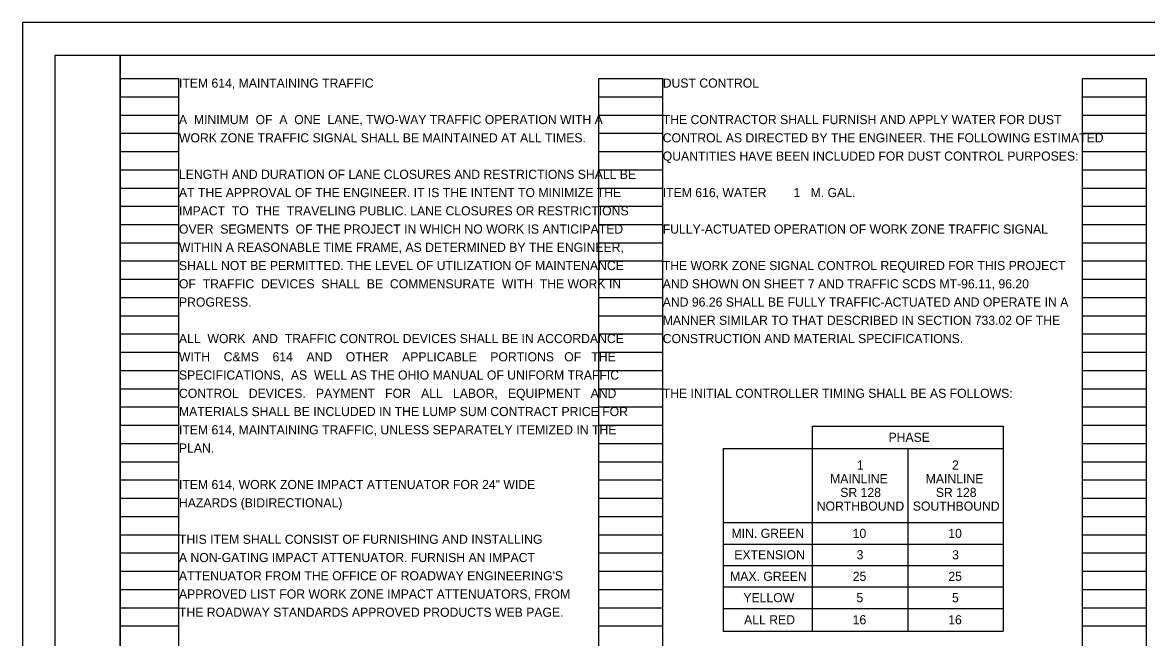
# Model space of a CAD drawing. Extents: x 0 to 34, y 0 to 22.
# Drawn here: x 0 to 17.24, y 12.56 to 22 of the extents above; entities that cross this region are included whole.
import ezdxf

# ---------------------------------------------------------------- set-up
doc = ezdxf.new("R2010")
doc.units = 0
for name, color, linetype in [('SH_Border', 7, 'Continuous'), ('SH_Cut_Line', 7, 'Continuous'), ('SH_Data', 7, 'Continuous'), ('SH_Text', 7, 'Continuous')]:
    doc.layers.add(name, color=color, linetype=linetype)

msp = doc.modelspace()

# ---------------------------------------------------------------- linework, layer by layer
at = {"layer": 'SH_Border'}
for points in [[(0.5, 21.5), (1.5, 21.5), (1.5, 0.5), (0.5, 0.5)], [(1.5, 21.5), (33.5, 21.5), (33.5, 0.5), (1.5, 0.5)]]:
    msp.add_lwpolyline(points, close=True, dxfattribs=at)
at = {"layer": 'SH_Cut_Line'}
msp.add_lwpolyline([(0, 0), (34, 0), (34, 22), (0, 22)], close=True, dxfattribs=at)
at = {"layer": 'SH_Data'}
for p, q in [((1.5, 0.98), (1.5, 21.14)), ((1.5, 21.14), (2.4, 21.14)), ((2.4, 0.98), (2.4, 21.14)), ((8.84, 0.98), (8.84, 21.14)), ((8.84, 21.14), (9.82, 21.14)), ((9.82, 0.98), (9.82, 21.14)), ((16.26, 0.98), (16.26, 21.14)), ((16.26, 21.14), (17.24, 21.14)), ((17.24, 0.98), (17.24, 21.14)), ((1.5, 20.86), (2.4, 20.86)), ((8.84, 20.86), (9.82, 20.86)), ((16.26, 20.86), (17.24, 20.86)), ((1.5, 20.58), (2.4, 20.58)), ((8.84, 20.58), (9.82, 20.58)), ((16.26, 20.58), (17.24, 20.58)), ((1.5, 20.3), (2.4, 20.3)), ((8.84, 20.3), (9.82, 20.3)), ((16.26, 20.3), (17.24, 20.3)), ((1.5, 20.02), (2.4, 20.02)), ((8.84, 20.02), (9.82, 20.02)), ((16.26, 20.02), (17.24, 20.02)), ((1.5, 19.74), (2.4, 19.74)), ((8.84, 19.74), (9.82, 19.74)), ((16.26, 19.74), (17.24, 19.74)), ((1.5, 19.46), (2.4, 19.46)), ((8.84, 19.46), (9.82, 19.46)), ((16.26, 19.46), (17.24, 19.46)), ((1.5, 19.18), (2.4, 19.18)), ((8.84, 19.18), (9.82, 19.18)), ((16.26, 19.18), (17.24, 19.18)), ((1.5, 18.9), (2.4, 18.9)), ((8.84, 18.9), (9.82, 18.9)), ((16.26, 18.9), (17.24, 18.9)), ((1.5, 18.62), (2.4, 18.62)), ((8.84, 18.62), (9.82, 18.62)), ((16.26, 18.62), (17.24, 18.62)), ((1.5, 18.34), (2.4, 18.34)), ((8.84, 18.34), (9.82, 18.34)), ((16.26, 18.34), (17.24, 18.34)), ((1.5, 18.06), (2.4, 18.06)), ((8.84, 18.06), (9.82, 18.06)), ((16.26, 18.06), (17.24, 18.06)), ((1.5, 17.78), (2.4, 17.78)), ((8.84, 17.78), (9.82, 17.78)), ((16.26, 17.78), (17.24, 17.78)), ((1.5, 17.5), (2.4, 17.5)), ((8.84, 17.5), (9.82, 17.5)), ((16.26, 17.5), (17.24, 17.5)), ((1.5, 17.22), (2.4, 17.22)), ((8.84, 17.22), (9.82, 17.22)), ((16.26, 17.22), (17.24, 17.22)), ((1.5, 16.94), (2.4, 16.94)), ((8.84, 16.94), (9.82, 16.94)), ((16.26, 16.94), (17.24, 16.94)), ((1.5, 16.66), (2.4, 16.66)), ((8.84, 16.66), (9.82, 16.66)), ((16.26, 16.66), (17.24, 16.66)), ((1.5, 16.38), (2.4, 16.38)), ((8.84, 16.38), (9.82, 16.38)), ((16.26, 16.38), (17.24, 16.38)), ((1.5, 16.1), (2.4, 16.1)), ((8.84, 16.1), (9.82, 16.1)), ((16.26, 16.1), (17.24, 16.1)), ((1.5, 15.82), (2.4, 15.82)), ((8.84, 15.82), (9.82, 15.82)), ((12.112, 15.808), (15.044, 15.808)), ((12.112, 15.808), (12.112, 12.662)), ((15.044, 15.808), (15.044, 12.662)), ((16.26, 15.82), (17.24, 15.82)), ((1.5, 15.54), (2.4, 15.54)), ((8.84, 15.54), (9.82, 15.54)), ((16.26, 15.54), (17.24, 15.54)), ((10.745, 15.462), (15.044, 15.462)), ((10.745, 15.462), (10.745, 12.662)), ((13.578, 15.462), (13.578, 14.326)), ((1.5, 15.26), (2.4, 15.26)), ((8.84, 15.26), (9.82, 15.26)), ((16.26, 15.26), (17.24, 15.26)), ((1.5, 14.98), (2.4, 14.98)), ((8.84, 14.98), (9.82, 14.98)), ((16.26, 14.98), (17.24, 14.98)), ((1.5, 14.7), (2.4, 14.7)), ((8.84, 14.7), (9.82, 14.7)), ((16.26, 14.7), (17.24, 14.7)), ((1.5, 14.42), (2.4, 14.42)), ((8.84, 14.42), (9.82, 14.42)), ((10.745, 14.326), (15.044, 14.326)), ((13.578, 14.326), (13.578, 12.662)), ((16.26, 14.42), (17.24, 14.42)), ((1.5, 14.14), (2.4, 14.14)), ((8.84, 14.14), (9.82, 14.14)), ((16.26, 14.14), (17.24, 14.14)), ((10.745, 13.996), (15.044, 13.996)), ((1.5, 13.86), (2.4, 13.86)), ((8.84, 13.86), (9.82, 13.86)), ((16.26, 13.86), (17.24, 13.86)), ((10.745, 13.667), (15.044, 13.667)), ((1.5, 13.58), (2.4, 13.58)), ((8.84, 13.58), (9.82, 13.58)), ((16.26, 13.58), (17.24, 13.58)), ((1.5, 13.3), (2.4, 13.3)), ((8.84, 13.3), (9.82, 13.3)), ((10.745, 13.338), (15.044, 13.338)), ((16.26, 13.3), (17.24, 13.3)), ((1.5, 13.02), (2.4, 13.02)), ((8.84, 13.02), (9.82, 13.02)), ((10.745, 13.008), (15.044, 13.008)), ((16.26, 13.02), (17.24, 13.02)), ((1.5, 12.74), (2.4, 12.74)), ((8.84, 12.74), (9.82, 12.74)), ((10.745, 12.662), (15.044, 12.662)), ((16.26, 12.74), (17.24, 12.74))]:
    msp.add_line(p, q, dxfattribs=at)

# ---------------------------------------------------------------- texts
at = {"layer": 'SH_Text'}
for s, p in [('ITEM 614, MAINTAINING TRAFFIC', (2.4, 21)), ('DUST CONTROL', (9.82, 21)), ('A  MINIMUM  OF  A  ONE  LANE, TWO-WAY TRAFFIC OPERATION WITH A', (2.4, 20.44)), ('THE CONTRACTOR SHALL FURNISH AND APPLY WATER FOR DUST', (9.82, 20.44)), ('WORK ZONE TRAFFIC SIGNAL SHALL BE MAINTAINED AT ALL TIMES.', (2.4, 20.16)), ('CONTROL AS DIRECTED BY THE ENGINEER. THE FOLLOWING ESTIMATED', (9.82, 20.16)), ('QUANTITIES HAVE BEEN INCLUDED FOR DUST CONTROL PURPOSES:', (9.82, 19.88)), ('LENGTH AND DURATION OF LANE CLOSURES AND RESTRICTIONS SHALL BE', (2.4, 19.6)), ('AT THE APPROVAL OF THE ENGINEER. IT IS THE INTENT TO MINIMIZE THE', (2.4, 19.32)), ('ITEM 616, WATER        1   M. GAL.', (9.82, 19.32)), ('IMPACT  TO  THE  TRAVELING PUBLIC. LANE CLOSURES OR RESTRICTIONS', (2.4, 19.04)), ('OVER  SEGMENTS  OF THE PROJECT IN WHICH NO WORK IS ANTICIPATED', (2.4, 18.76)), ('FULLY-ACTUATED OPERATION OF WORK ZONE TRAFFIC SIGNAL', (9.82, 18.76)), ('WITHIN A REASONABLE TIME FRAME, AS DETERMINED BY THE ENGINEER,', (2.4, 18.48)), ('SHALL NOT BE PERMITTED. THE LEVEL OF UTILIZATION OF MAINTENANCE', (2.4, 18.2)), ('THE WORK ZONE SIGNAL CONTROL REQUIRED FOR THIS PROJECT', (9.82, 18.2)), ('OF  TRAFFIC  DEVICES  SHALL  BE  COMMENSURATE  WITH  THE WORK IN', (2.4, 17.92)), ('AND SHOWN ON SHEET 7 AND TRAFFIC SCDS MT-96.11, 96.20', (9.82, 17.92)), ('PROGRESS.', (2.4, 17.64)), ('AND 96.26 SHALL BE FULLY TRAFFIC-ACTUATED AND OPERATE IN A', (9.82, 17.64)), ('MANNER SIMILAR TO THAT DESCRIBED IN SECTION 733.02 OF THE', (9.82, 17.36)), ('ALL  WORK  AND  TRAFFIC CONTROL DEVICES SHALL BE IN ACCORDANCE', (2.4, 17.08)), ('CONSTRUCTION AND MATERIAL SPECIFICATIONS.', (9.82, 17.08)), ('WITH    C&MS    614    AND    OTHER    APPLICABLE    PORTIONS   OF   THE', (2.4, 16.8)), ('SPECIFICATIONS,  AS  WELL AS THE OHIO MANUAL OF UNIFORM TRAFFIC', (2.4, 16.52)), ('CONTROL   DEVICES.   PAYMENT   FOR   ALL   LABOR,   EQUIPMENT   AND', (2.4, 16.24)), ('THE INITIAL CONTROLLER TIMING SHALL BE AS FOLLOWS:', (9.82, 16.24)), ('MATERIALS SHALL BE INCLUDED IN THE LUMP SUM CONTRACT PRICE FOR', (2.4, 15.96)), ('ITEM 614, MAINTAINING TRAFFIC, UNLESS SEPARATELY ITEMIZED IN THE', (2.4, 15.68)), ('PHASE', (13.283, 15.565)), ('PLAN.', (2.4, 15.4)), ('1', (12.799, 15.139)), ('2', (14.258, 15.139)), ('MAINLINE', (12.387, 14.929)), ('MAINLINE', (13.853, 14.929)), ('ITEM 614, WORK ZONE IMPACT ATTENUATOR FOR 24" WIDE', (2.4, 14.84)), ('SR 128', (12.543, 14.719)), ('SR 128', (14.009, 14.719)), ('HAZARDS (BIDIRECTIONAL)', (2.4, 14.56)), ('NORTHBOUND', (12.182, 14.509)), ('SOUTHBOUND', (13.656, 14.509)), ('THIS ITEM SHALL CONSIST OF FURNISHING AND INSTALLING', (2.4, 14)), ('MIN. GREEN', (10.875, 14.091)), ('10', (12.733, 14.091)), ('10', (14.199, 14.091)), ('A NON-GATING IMPACT ATTENUATOR. FURNISH AN IMPACT', (2.4, 13.72)), ('EXTENSION', (10.918, 13.762)), ('3', (12.793, 13.762)), ('3', (14.259, 13.762)), ("ATTENUATOR FROM THE OFFICE OF ROADWAY ENGINEERING'S", (2.4, 13.44)), ('MAX. GREEN', (10.853, 13.432)), ('25', (12.735, 13.432)), ('25', (14.201, 13.432)), ('APPROVED LIST FOR WORK ZONE IMPACT ATTENUATORS, FROM', (2.4, 13.16)), ('YELLOW', (11.057, 13.103)), ('5', (12.791, 13.103)), ('5', (14.257, 13.103)), ('THE ROADWAY STANDARDS APPROVED PRODUCTS WEB PAGE.', (2.4, 12.88)), ('ALL RED', (11.068, 12.765)), ('16', (12.733, 12.765)), ('16', (14.199, 12.765))]:
    msp.add_text(s, height=0.14, dxfattribs=at).set_placement(p)

doc.saveas('drawing.dxf')
